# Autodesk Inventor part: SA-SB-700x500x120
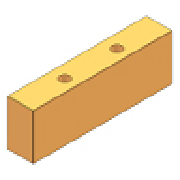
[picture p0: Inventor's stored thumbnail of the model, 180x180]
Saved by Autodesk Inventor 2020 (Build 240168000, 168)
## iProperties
Created: 2019-01
Part Number: SA-SB-700x500x120
Material: S 55 C
Description: Spacer Block
Document SubType Name: Modeling
Designer: LENOVO-CADCIM
Standard Revision: 1
Manufacturer: FUTABA
Language: en-US
Size Designation: 700x500x120
Categories: <MemberInstance><Categories><Category DisplayName="Mold" InternalName="349578f2-f4d4-4954-8c09-8e99297a61c0" Mnemonic="MOLD"><Category DisplayName="Mold Plates"
Density: 7.85 g/cm^3
Appearance: Orange (Pale)
IsCustomPart: 1
Author: LENOVO-CADCIM
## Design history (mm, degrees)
sketch "Sketch1"
  geometry: L1 (-162, 350)-(-250, 350); L2 (-250, 350)-(-250, -350); L3 (-250, -350)-(-162, -350); L4 (-162, -350)-(-162, 350); L5 (250, 350)-(250, -350); L6 (162, -350)-(162, 350); L7 (162, 350)-(250, 350); L8 (162, -350)-(250, -350); 5 further points
  constraints: 16 end point, 3 parallel, 2 horizontal alignment, 2 midpoint, 2 perpendicular, 1 horizontal, 1 vertical
  dimensions: "d85" = 700 distance between parallel lines of L3 L1 (= L); "d86" = 88 distance between parallel lines of L4 L2 (= W_); "d88" = 88 distance between parallel lines of L5 L6 (= W_); "d89" = 250 distance from line of point (0, 0) L2 (= 0.5 x M_W); "d93" = 700 distance between parallel lines of L8 L7 (= L); "d94" = 250 distance from line of point (0, 0) L5 (= 0.5 x M_W); "d98" = 243 vertical distance of point (-205, 243) point (0, 0) (= 0.5 x S1_L); "d100" = 205 horizontal distance of point (-205, 243) point (0, 0) (= 0.5 x S1_W); "d101" = 205 horizontal distance of point (205, 243) point (0, 0) (= 0.5 x S1_W); "d102" = 243 vertical distance of point (0, 0) point (205, 243) (= 0.5 x S1_L)
extrude "Extrusion1" new body sketch "Sketch1" distance "d20" = 120 (= H_); taper "d30" = 0 deg
extrude "Extrusion2" join sketch "Sketch1" distance "d95" = 120 (= H_); taper "d96" = 0 deg
workplane "Work Plane2"
body "Solid1"
hole "Hole1" sketch "Sketch1" diameter "d129" = 18 (= S1_d1); stored, may be unused: countersink angle "d133" = 90 deg, drill point angle "d135" = 0 deg; dims "d130" = 6, "d131" = 4, "d132" = 2, "d134" = 120 (= H_)
pattern_linear "Rectangular Pattern1" dims "d156" = 243 (computed from S1_L, Ns)
hole "Hole2" sketch "Sketch1" diameter "d122" = 18 (= S1_d1); stored, may be unused: countersink angle "d126" = 90 deg, drill point angle "d128" = 0 deg; dims "d123" = 6, "d124" = 4, "d125" = 2, "d127" = 120 (= H_)
pattern_linear "Rectangular Pattern2" dims "d153" = 243 (computed from S1_L, Ns)
workplane "Work Plane1"
chamfer "Chamfer1" distance "d157" = 0.5; stored, may be unused: second distance "d158" = 2, angle "d159" = 45 deg
chamfer "Chamfer2" distance "d160" = 0.5; stored, may be unused: second distance "d161" = 2, angle "d162" = 45 deg
other parameters: "L" = 700 [user parameter; used in 2 equation terms], "W_" = 88 [user parameter; used in 2 equation terms], "H_" = 120 [user parameter; used in 5 equation terms], "S1_L" = 486 [user parameter; used in 4 equation terms], "S1_d1" = 18 [user parameter; used in 2 equation terms], "d164" = 0
